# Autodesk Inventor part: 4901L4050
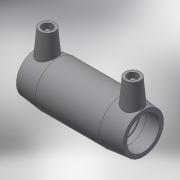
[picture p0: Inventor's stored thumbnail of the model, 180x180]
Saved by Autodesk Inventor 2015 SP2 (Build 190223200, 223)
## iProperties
Created: 2017-06
Part Number: 4901L4050
Material: Generic
Description: PLASSON LONG COUPLER 50
Document SubType Name: Modeling
Designer: KIM
Mass: 72.9589 g
Surface Area: 285.531 cm^2
Volume: 72.9589 cm^3
Density: 1 g/cm^3
Appearance: Default
Author: KIM
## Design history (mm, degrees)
derived "4901L4.ipt"
feature "Solid1::4901L4.ipt"
tag "TaggingFeature1"
body "Solid1"
other parameters: "d0" = 139, "d2" = 68, "d3" = 68, "d4" = 27.8, "d5" = 61.2, "d8" = 168 deg, "d10" = 27.2, "d11" = 9.06667, "d29" = 51, "d30" = 15, "d31" = 55.6, "d34" = 5 deg, "d41" = 4, "d42" = 14, "d43" = 0, "d48" = 3, "d49" = 0, "L_" = 139, "L_1" = 68, "D_" = 68, "A_" = 51, "d_2" = 12
